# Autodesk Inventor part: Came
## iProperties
Author: Flavien MARTY
Shininess: 20.0
PropertySet Name: _Private Model Information
Created: 2001-10
Part Number: Came
Material: Par défaut
Document SubType Name: Modélisation
Designer: Flavien MARTY
Control State: 0
Master: False
Checked Out: False
PropertySet Name: Design Tracking Control
Density: 0.0
Volumn: 0.0
Area: 0.0
PropertySet Name: Model Information
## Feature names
1. Base1
